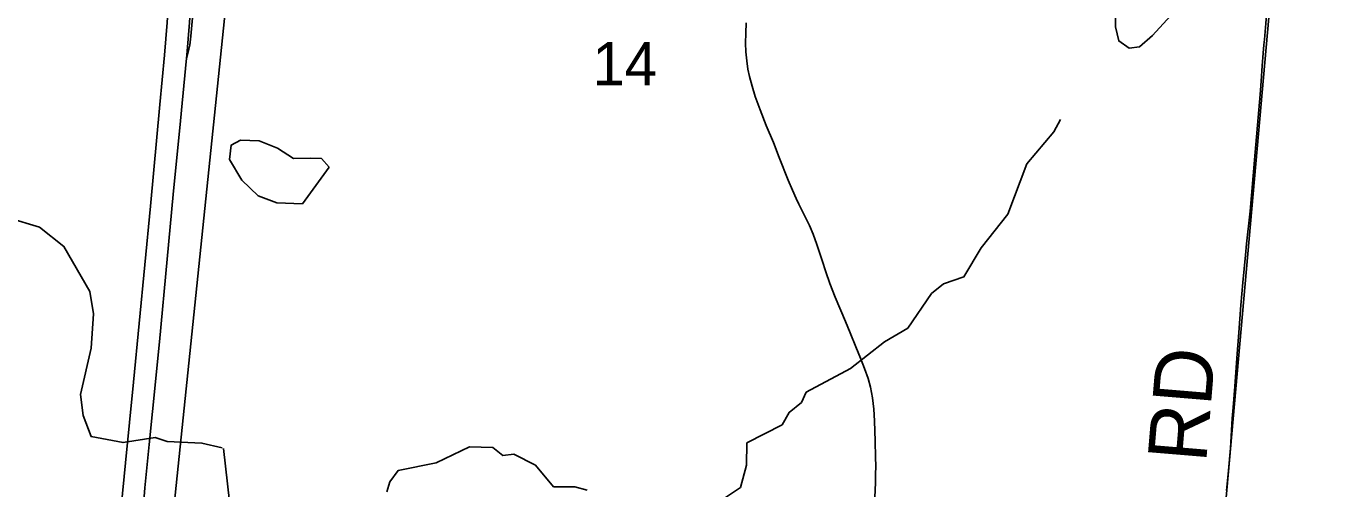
# Model space of a CAD drawing. Extents: x 0 to 34, y 0 to 22.
# Drawn here: x 26.894 to 28.153, y 16.574 to 17.021 of the extents above; entities that cross this region are included whole.
import ezdxf

# ---------------------------------------------------------------- set-up
doc = ezdxf.new("R2010")
doc.units = 0
for name, color, linetype in [('GM_X_County_Road', 7, 'Continuous'), ('GM_X_Interchange_Ramps', 7, 'Continuous'), ('GM_X_Interstate_Route', 7, 'Continuous'), ('GM_X_Minor_Lake', 7, 'Continuous'), ('GM_X_Minor_River', 7, 'Continuous'), ('GM_X_Section', 7, 'Continuous'), ('GM_X_Section_Text', 7, 'Continuous'), ('GM_X_Township_Road', 7, 'Continuous'), ('GM_X_Township_Road_Text', 7, 'Continuous')]:
    doc.layers.add(name, color=color, linetype=linetype)

msp = doc.modelspace()

# ---------------------------------------------------------------- linework, layer by layer
at = {"layer": 'GM_X_County_Road'}
msp.add_lwpolyline([(27.7141, 16.5517), (27.7152, 16.5796), (27.7154, 16.5876), (27.7155, 16.5957), (27.7154, 16.6044), (27.715, 16.6198), (27.7144, 16.6397), (27.7137, 16.6508), (27.7124, 16.6618), (27.7103, 16.672), (27.708, 16.6804), (27.7046, 16.6903), (27.7008, 16.7001), (27.6963, 16.711), (27.6906, 16.7248), (27.6861, 16.7357), (27.6763, 16.7591), (27.671, 16.7724), (27.6671, 16.7835), (27.6635, 16.7947), (27.6586, 16.81), (27.655, 16.8199), (27.6514, 16.8284), (27.6451, 16.8412), (27.6412, 16.849), (27.6385, 16.8546), (27.635, 16.8625), (27.6309, 16.8723), (27.6222, 16.8942), (27.6165, 16.9086), (27.6096, 16.9252), (27.6036, 16.9402), (27.599, 16.9531), (27.5958, 16.9632), (27.5934, 16.9723), (27.5919, 16.9796), (27.5907, 16.9877), (27.5899, 16.9964), (27.5896, 17.0045), (27.5897, 17.0144), (27.5901, 17.0244)], dxfattribs=at)
at = {"layer": 'GM_X_Interchange_Ramps'}
msp.add_lwpolyline([(27.0488, 16.9901), (27.0511, 16.9987), (27.052, 17.0028), (27.053, 17.0113), (27.0546, 17.0291), (27.0562, 17.047), (27.0586, 17.0811), (27.0601, 17.0959), (27.0623, 17.1132), (27.0655, 17.1334), (27.0698, 17.1553), (27.0751, 17.1783), (27.0807, 17.2), (27.0882, 17.2256), (27.1001, 17.2642), (27.1105, 17.2973), (27.1172, 17.3167), (27.1189, 17.3213)], dxfattribs=at)
at = {"layer": 'GM_X_Interstate_Route'}
for points in [[(26.9856, 16.556), (26.9898, 16.599), (26.9975, 16.6769), (27.0138, 16.847), (27.0231, 16.9454), (27.0276, 16.993), (27.0301, 17.0246), (27.0307, 17.0341), (27.0364, 17.1194), (27.0412, 17.1951), (27.0473, 17.2937), (27.053, 17.3873), (27.0569, 17.4456), (27.0586, 17.4728), (27.061, 17.5095), (27.0645, 17.5672), (27.0704, 17.6608), (27.0734, 17.7072), (27.0774, 17.7668), (27.0815, 17.8375), (27.0829, 17.8611), (27.0872, 17.9274)], [(27.0429, 16.9297), (27.0445, 16.9466), (27.0488, 16.9901), (27.0491, 16.993), (27.0517, 17.0245), (27.0548, 17.0735), (27.0591, 17.1442), (27.0625, 17.1976)], [(27.0127, 16.6167), (27.0158, 16.6485), (27.0225, 16.7159), (27.0299, 16.7957), (27.036, 16.8582), (27.0429, 16.9297)], [(26.9984, 16.4669), (27.0032, 16.5155), (27.0067, 16.5538), (27.0086, 16.5749), (27.0127, 16.6167)]]:
    msp.add_lwpolyline(points, dxfattribs=at)
at = {"layer": 'GM_X_Minor_Lake'}
for points in [[(27.9813, 17.1071), (27.9859, 17.0911), (27.9852, 17.0774), (27.9755, 17.0644), (27.9644, 17.0589), (27.9517, 17.0489), (27.9473, 17.0361), (27.9474, 17.0205), (27.9505, 17.0068), (27.9606, 16.9997), (27.9705, 17.0011), (27.9832, 17.0122), (28.0532, 17.0886), (28.0485, 17.1004), (28.0423, 17.1089), (28.0386, 17.1181)], [(27.1867, 16.8848), (27.1792, 16.8933), (27.1683, 16.8935), (27.1524, 16.8931), (27.1367, 16.9033), (27.119, 16.9101), (27.1009, 16.9109), (27.0921, 16.9061), (27.0903, 16.8921), (27.1024, 16.8721), (27.118, 16.857), (27.136, 16.8502), (27.161, 16.8493)], [(27.161, 16.8493), (27.1867, 16.8848)]]:
    msp.add_lwpolyline(points, dxfattribs=at)
at = {"layer": 'GM_X_Minor_River'}
for points in [[(27.5644, 16.5615), (27.5847, 16.5752), (27.5905, 16.5967), (27.5909, 16.6183), (27.6249, 16.6358), (27.6316, 16.6478), (27.6435, 16.6574), (27.6482, 16.6672), (27.6911, 16.6902), (27.7238, 16.7161), (27.7464, 16.729), (27.7693, 16.7626), (27.7809, 16.7719), (27.8007, 16.7787), (27.8175, 16.8068), (27.8431, 16.8393), (27.8615, 16.8879), (27.8879, 16.9189), (27.8942, 16.9309)], [(27.0833, 16.6135), (27.0637, 16.6181), (27.03, 16.6195), (27.0183, 16.6235), (26.9874, 16.6185), (26.9565, 16.6244), (26.9489, 16.6447), (26.9463, 16.6649), (26.9567, 16.7099), (26.9588, 16.7429), (26.9551, 16.7647), (26.9302, 16.8081), (26.9067, 16.8268), (26.8765, 16.8358)], [(27.0844, 16.613), (27.0959, 16.5134)], [(27.2425, 16.5709), (27.2454, 16.5807), (27.2535, 16.5915), (27.2904, 16.5991), (27.3225, 16.6144), (27.3452, 16.6139), (27.3549, 16.6061), (27.3655, 16.6074), (27.3865, 16.5967), (27.4038, 16.5759), (27.4243, 16.5758), (27.4363, 16.5725)]]:
    msp.add_lwpolyline(points, dxfattribs=at)
at = {"layer": 'GM_X_Section'}
for points in [[(27.1399, 17.5549), (27.036, 16.5489), (26.0294, 16.6508), (26.1215, 17.6588)], [(27.1399, 17.5549), (28.1329, 17.4467), (28.0435, 16.442), (27.036, 16.5489)], [(28.1329, 17.4467), (29.1277, 17.3507), (29.042, 16.3387), (28.0435, 16.442)]]:
    msp.add_lwpolyline(points, close=True, dxfattribs=at)
at = {"layer": 'GM_X_Township_Road'}
for points in [[(28.0742, 16.8107), (28.0776, 16.8424), (28.0806, 16.8764), (28.0823, 16.8956), (28.0832, 16.9068), (28.0854, 16.9327), (28.0874, 16.9549), (28.0882, 16.9679), (28.0894, 16.9827), (28.0904, 16.9951), (28.091, 17.0031), (28.0914, 17.0081), (28.0927, 17.0235), (28.0944, 17.0457), (28.0958, 17.063), (28.0975, 17.0784), (28.0979, 17.0827), (28.0986, 17.0882), (28.0999, 17.0993), (28.101, 17.1098), (28.1023, 17.1218)], [(28.0548, 16.5724), (28.0568, 16.5916), (28.0587, 16.6133), (28.0604, 16.6418), (28.0612, 16.6524), (28.0628, 16.6728), (28.0648, 16.7001), (28.0666, 16.7249), (28.0687, 16.7515), (28.0705, 16.7732), (28.073, 16.7998), (28.0742, 16.8107)]]:
    msp.add_lwpolyline(points, dxfattribs=at)

# ---------------------------------------------------------------- texts
at = {"layer": 'GM_X_Section_Text'}
msp.add_text('14', height=0.04186, rotation=0, dxfattribs=at).set_placement((27.4415, 16.9638))
at = {"layer": 'GM_X_Township_Road_Text'}
msp.add_text('RD', height=0.05682, rotation=85.2329, dxfattribs=at).set_placement((28.035, 16.5984))

doc.saveas('drawing.dxf')
